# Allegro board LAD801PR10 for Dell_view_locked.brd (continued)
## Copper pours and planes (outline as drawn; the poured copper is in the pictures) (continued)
GND on IN2 (solid shape): 12.56,102.92 12.3,102.19 11.64,101.79 11.4,102.02 9.35,102.02 9.09,101.76 7.96,101.76 7.96,101.52 7.62,100.7 6.8,100.36 6,100.36 5.18,100.7 4.84,101.52 4.84,101.76 3.86,101.76 3.6,102.02 1.68,102.02 1.42,101.76 1,101.76 0.76,101.66 0.66,101.42 0.66,100.8 0.76,100.56 1,100.46 1.8,100.46 2.83,100.03 3.26,99 3.26,98.15 3.68,97.73 11.7,97.73 13.28,96.16 13.28,93.95 12.8,93.46 9.65,93.46 9.65,94.75 9.07,95.44 8.29,94.99 8.28,94.95 1,94.95 0.44,95.19 0.2,95.75 0.2,96.9 0.44,97.46 1,97.7 1.8,97.7 2.51,97.99 2.8,98.7 2.8,99 2.51,99.71 1.8,100 1,100 0.44,100.24 0.2,100.8 0.2,101.42 0.44,101.99 1,102.22 5,102.22 5.21,102.13 5.3,101.92 5.3,101.52 5.5,101.03 6,100.82 6.8,100.82 7.3,101.03 7.5,101.52 7.5,101.92 7.59,102.13 7.8,102.22 11.4,102.22 11.9,102.43 12.1,102.92 12.1,103.62 12.56,103.62
GND on IN2 (solid shape): outline of 339 points within 77.84,101.24 84.51,110.87
GND on IN2 (solid shape): outline of 281 points within 0.2,0.2 231.7,138.3
GND on IN3 (solid shape): 67.32,125.11 67.32,121.66 66.87,121.21 65.81,121.21 65.6,121.01 65.6,119.97 65.95,119.63 67.11,119.63 67.32,119.42 67.32,117.11 67.03,116.82 61.73,116.82 61.48,117.07 61.48,124.47 62.69,125.68 66.75,125.68
GND on IN3 (solid shape): 158.72,71.6 158.72,69.45 157.12,67.85 157.12,63.21 156.74,62.83 154.92,62.83 151.79,65.96 151.79,68.12 152.24,68.57 153.59,68.57 155.44,70.41 155.44,71.36 155.8,71.72 155.83,71.72 155.86,71.75 158.56,71.75
GND on IN3 (solid shape): 158.77,81.33 158.77,79.08 158.39,78.7 158.39,74.51 158.32,74.45 152.13,74.45 151.94,74.63 151.94,78.15 152.3,78.51 154.26,78.51 154.4,78.64 154.71,78.64 155.49,79.42 155.49,80.73 156.13,81.37 156.18,81.37 156.3,81.49 158.6,81.49
GND on IN3 (solid shape): 14.7,31.39 14.7,29.2 13.71,28.21 13.71,26.97 13.46,26.71 2.49,26.71 2.5,26.81 2.5,26.9 2.5,30.17 2.74,30.73 3.3,30.96 12.28,30.96 12.79,31.18 12.98,31.69 14.4,31.69
GND on IN3 (solid shape): 14.57,52.82 14.57,51.58 13.96,50.97 13.96,47.03 14.42,46.58 14.42,45.32 13.44,44.34 12.98,44.34 12.77,44.83 12.28,45.04 3.3,45.04 2.74,45.27 2.5,45.83 2.5,51.87 2.74,52.43 3.3,52.66 12.28,52.66 12.73,52.82 12.97,53.23 14.17,53.23
GND on IN3 (solid shape): 13.53,80.13 13.53,69.33 14.47,68.39 14.47,67.15 14.01,66.69 12.53,66.69 12.41,66.72 12.28,66.74 4.3,66.74 3.74,66.97 3.5,67.53 3.5,75.1 3.18,75.92 1.87,76.55 1.66,77.09 1.66,78.25 1.9,78.81 2.46,79.05 8.28,79.05 8.29,79.01 9.07,78.56 9.65,79.25 9.65,80.82 12.85,80.82
GND on IN3 (solid shape): 12.56,102.92 12.3,102.19 11.64,101.79 11.4,102.02 9.35,102.02 9.09,101.76 7.96,101.76 7.96,101.52 7.62,100.7 6.8,100.36 6,100.36 5.18,100.7 4.84,101.52 4.84,101.76 3.86,101.76 3.6,102.02 1.68,102.02 1.42,101.76 1,101.76 0.76,101.66 0.66,101.42 0.66,100.8 0.76,100.56 1,100.46 1.8,100.46 2.83,100.03 3.26,99 3.26,98.15 3.68,97.73 11.7,97.73 13.28,96.16 13.28,93.95 12.8,93.46 9.65,93.46 9.65,94.75 9.07,95.44 8.29,94.99 8.28,94.95 1,94.95 0.44,95.19 0.2,95.75 0.2,96.9 0.44,97.46 1,97.7 1.8,97.7 2.51,97.99 2.8,98.7 2.8,99 2.51,99.71 1.8,100 1,100 0.44,100.24 0.2,100.8 0.2,101.42 0.44,101.99 1,102.22 5,102.22 5.21,102.13 5.3,101.92 5.3,101.52 5.5,101.03 6,100.82 6.8,100.82 7.3,101.03 7.5,101.52 7.5,101.92 7.59,102.13 7.8,102.22 11.4,102.22 11.9,102.43 12.1,102.92 12.1,103.62 12.56,103.62
GND on IN3 (solid shape): outline of 279 points within 0.2,0.2 231.7,138.3
GND on GND1: outline of 262 points within 0.2,0.2 231.7,138.3
GND on VCC: outline of 213 points within 1.17,17.35 230.73,137.33
GND on VCC: 2.77,1.17 2.77,6.93 3.65,6.93 5.27,7.69 5.74,9.42 26.6,9.42 27.62,10.44 31.2,10.44 31.2,1.17
GND on GND2: outline of 263 points within 0.2,0.2 231.7,138.3
VCCSA_B+ on BOTTOM (solid shape): 150.08,63.13 150.08,62.73 149.55,62.73 149.55,62.29 150.08,62.29 150.08,61.57 149.69,61.17 149.69,58 149.56,57.87 148.29,57.87 146.39,55.97 146.32,55.97 146.01,56.28 146.01,56.35 146.39,56.73 146.39,56.86 145.81,57.43 145.81,58.06 145.83,58.08 146.71,59.76 146.9,61.66 146.89,61.68 148.42,63.21 150,63.21
+BIF_VDDC on TOP (solid shape): 114.59,118.51 114.59,117.8 114.59,117.75 114.5,117.66 114,117.66 113.86,117.8 113.15,117.8 113.06,117.89 111.99,117.89 111.81,118.07 111.81,118.6 111.99,118.78 114.32,118.78
+BIF_VDDC on TOP (solid shape): 112.42,124.54 112.42,123.86 113.02,123.25 113.02,123.04 112.97,123.04 112.97,122.94 112.66,122.63 111.01,122.63 110.77,122.88 110.79,122.91 110.79,123.28 110.46,123.45 110.38,123.48 110.35,123.56 110.35,124.63 110.38,124.67 112.29,124.67
+BIF_VDDC on IN3 (solid shape): outline of 433 points within 110.73,117.8 115.31,123.81
+DCBAT_LCD on TOP (solid shape): 229.17,52.71 229.17,49.67 228.73,49.23 225.07,49.23 224.78,49.52 224.78,49.58 224.68,49.68 223.31,49.68 223.11,49.88 223.11,51.43 223.37,51.69 225.24,51.69 225.6,52.05 225.6,52.76 226.02,53.18 228.7,53.18
+DCBAT_LCD on BOTTOM (solid shape): 225.45,50.32 225.45,49.45 225.34,49.34 223.52,49.34 223.4,49.45 223.4,50.32 223.65,50.57 225.2,50.57
+LAN_VDD33 on TOP (solid shape): 39.14,115.59 39.14,113.8 38.76,113.42 36.71,113.42 36.59,113.53 36.59,115.28 36.77,115.46 37.86,115.46 38.12,115.72 39.01,115.72
+LAN_VDD33 on BOTTOM (solid shape): 37.36,115.4 37.74,115.4 37.86,115.28 37.86,114.45 37.74,114.32 36.84,114.32 36.4,114.76 36.4,115.47 36.47,115.53 37.23,115.53
+LAN_VDD33 on BOTTOM (solid shape): 30.38,121.51 30.82,121.51 30.82,122.04 31.1,122.04 31.14,122 31.14,120.4 31.04,120.29 28.44,120.29 28.34,120.4 28.34,121.27 28.57,121.51 29.91,121.51 29.98,121.58 29.98,121.95 30.07,122.04 30.38,122.04
+LAN_VDD33 on IN1 (solid shape): 37.32,120.25 37.32,115.79 37.57,115.53 38.03,115.53 38.2,115.37 38.2,114.23 38.07,114.1 36.37,114.1 36.29,114.19 36.29,119.63 36.27,119.65 36.27,119.97 35.71,120.54 34.66,120.54 34.17,120.05 30.02,120.05 29.96,120.11 29.96,120.76 30.31,121.1 33.42,121.1 33.93,121.62 35.95,121.62
+LAN_VDDREG on TOP (solid shape): 37.49,119.59 37.49,118.76 37.29,118.57 35.52,118.57 35.45,118.64 35.45,119.78 35.2,120.03 35.2,120.22 35.39,120.41 36.66,120.41
+LAN_VDDREG on BOTTOM (solid shape): 36.02,119.97 36.02,119.59 35.9,119.46 35.9,118.57 35.83,118.51 35.71,118.51 35.64,118.57 35.64,119.46 35.45,119.65 35.45,119.84 35.2,120.1 35.2,120.29 35.33,120.41 35.58,120.41
+LCDVDD on BOTTOM (solid shape): 223.91,26.61 223.91,25.06 224.29,24.68 224.66,24.68 224.99,24.35 224.99,24.1 224.7,23.81 224.32,23.81 224.03,23.93 223.76,23.79 223.08,23.79 222.21,24.66 222.21,26.73 222.28,26.8 223.72,26.8
+LCDVDD_LCD on TOP (solid shape): 223.22,47.76 224.02,47.76 224.1,47.69 224.1,46.29 224.05,46.24 222.34,46.24 222.14,46.44 222.14,47.83 222.27,47.96 223.03,47.96
+LCDVDD_LCD on BOTTOM (solid shape): 223.34,47.76 224.49,47.76 224.58,47.67 224.58,46.44 224.5,46.37 222.46,46.37 222.33,46.49 222.33,46.5 222.2,46.63 222.2,47.73 222.38,47.91 223.19,47.91
+LCDVDD_LCD on BOTTOM (solid shape): 225.06,28.78 225.06,27.77 224.82,27.53 224.65,27.53 224.43,27.6 224.23,27.49 222.29,27.49 222.21,27.57 222.21,28.74 222.38,28.9 224.94,28.9
+LCDVDD_LCD on IN1 (solid shape): 223.6,47.71 223.6,47.64 223.61,47.63 223.61,45.6 223.53,45.52 222.6,45.52 222.54,45.58 222.3,45.58 222.02,45.87 222.02,47.77 222.27,48.02 223.29,48.02
+LCDVDD_LCD on IN1 (solid shape): 223.56,28.75 224.78,28.75 224.94,28.59 224.94,27.64 224.67,27.37 223.42,27.37 222.23,28.56 222.23,28.9 222.73,29.4 222.91,29.4
+LCDVDD_LCD on IN3 (solid shape): 226.38,28.62 226.38,27.02 226.19,26.83 224.01,26.83 223.9,26.94 223.9,28.64 223.98,28.72 226.28,28.72
+LCDVDD_LCD on IN3 (solid shape): 224.75,48.21 224.75,47.07 224.37,46.69 222.46,46.69 222.21,46.94 222.21,48.02 222.33,48.15 223.03,48.15 223.29,48.41 224.56,48.41
+PCIE_VDDC on TOP (solid shape): 116.42,123.97 116.42,122.94 116.81,122.54 116.81,121.19 116.65,121.03 116.65,119.75 116.31,119.4 115.51,119.4 115.08,118.98 111.43,118.98 110.97,119.44 110.97,120.23 111.06,120.31 114.22,120.31 114.38,120.48 114.38,121.29 114.24,121.43 114,121.43 113.94,121.49 113.94,121.67 114.92,121.67 114.92,121.61 114.92,121.56 114.94,121.51 114.96,121.46 114.99,121.42 115.03,121.38 115.07,121.34 115.12,121.32 115.17,121.3 115.22,121.29 115.27,121.28 115.33,121.29 115.38,121.3 115.43,121.32 115.47,121.34 115.52,121.38 115.55,121.42 115.58,121.46 115.6,121.51 115.62,121.56 115.63,121.61 115.63,121.67 115.62,121.72 115.6,121.77 115.58,121.82 115.55,121.86 115.52,121.9 115.47,121.93 115.43,121.96 115.38,121.98 115.33,121.99 115.27,122 115.22,121.99 115.17,121.98 115.12,121.96 115.07,121.93 115.03,121.9 114.99,121.86 114.96,121.82 114.94,121.77 114.92,121.72 114.92,121.67 113.94,121.67 113.94,122.95 114.19,123.21 114.19,123.53 114,123.72 113.62,123.72 113.6,123.69 113.58,123.69 113.48,123.59 113.43,123.59 113.16,123.86 113.11,123.93 113.11,124.03 114,124.92 115.46,124.92
+PCIE_VDDC on BOTTOM (solid shape): 105.68,102.19 105.68,101.17 106.11,100.74 106.11,99.13 105.65,98.67 105.65,97.64 106.11,97.17 106.11,96.14 105.87,95.9 103.61,95.9 103.55,95.97 103.55,97.33 103.71,97.48 103.71,101.29 103.97,101.55 103.99,101.56 104.19,101.66 104.29,101.86 104.29,101.88 104.67,102.25 105.62,102.25
+PCIE_VDDC on IN1 (solid shape): outline of 1893 points within 101.87,100.79 117.05,123.88
+SPLL_VDDC on TOP (solid shape): 121.15,105.13 121.15,104.71 122.24,103.62 122.27,103.54 122.23,103.47 122.12,103.04 122.52,102.83 122.54,102.84 122.64,102.74 122.64,99.84 122.45,99.65 121.88,99.65 121.68,99.85 121.68,101.74 121.06,102.36 121.06,102.46 121.09,102.54 121.18,102.56 121.62,102.99 121.03,103.17 121,103.16 120.96,103.17 120.43,103.71 120.43,104.89 120.43,104.89 120.43,105.13 120.61,105.31 120.97,105.31
+VGA_CORE on TOP (solid shape): 105.7,107.04 105.7,106.69 106,106.39 106,106.01 106.42,105.58 106.42,105.32 104.58,103.48 103.66,102.56 103.19,102.56 102.47,103.28 102.47,103.3 102,103.77 102,104.84 104.85,107.7 105.04,107.7
+VGA_CORE on TOP (solid shape): 111.53,105.53 111.53,103.98 111.38,103.82 111.32,103.61 111.32,102.62 111.47,102.47 111.45,102.44 111.45,101.89 111.37,101.89 111.37,101.66 111.37,101.65 111.35,101.51 111.37,101.37 111.37,101.36 111.37,101.3 111.26,101.18 107.91,101.18 107.65,101.43 107.65,102.32 108.22,102.89 108.22,103.2 108.32,103.3 108.32,103.3 108.86,103.85 109.26,103.85 109.56,104.15 109.56,104.86 110.1,105.4 110.1,105.58 110.29,105.77 111.29,105.77
+VGA_CORE on TOP (solid shape): outline of 120 points within 79.59,110.05 89.25,131.84
+VGA_CORE on BOTTOM (solid shape): 108.16,113.18 108.16,113.15 108.22,112.62 108.75,112.67 108.92,112.67 109.11,112.48 109.11,112.08 109.11,112.07 109.14,111.71 109.46,111.54 109.48,111.54 109.56,111.46 109.75,111.46 110.07,111.14 110.07,111.02 109.32,110.27 109.31,110.27 109.19,110.19 109.11,110.06 109.1,110.05 108.48,109.43 107.53,109.43 107.4,109.3 107.07,109.3 107.01,109.35 106.94,109.39 106.93,109.39 106.89,109.43 106.89,109.75 106.94,109.8 106.95,109.8 107.09,109.88 107.18,110.02 107.18,110.04 107.5,110.36 107.65,110.72 107.37,111 107.35,111 107.16,111.19 107.17,111.22 107.18,111.4 107.08,111.56 107.08,112.01 107.14,112.07 107.14,112.34 107.19,112.56 107.08,112.76 107.08,113.05 107.4,113.37 107.97,113.37
+VGA_CORE on BOTTOM (solid shape): outline of 139 points within 79.52,109.62 90.5,132.42
+VGA_CORE on BOTTOM (solid shape): 116.88,117.73 116.88,117.71 116.91,117.57 116.99,117.45 116.99,116.99 116.88,116.72 116.99,116.45 116.99,115.99 116.88,115.72 116.99,115.45 116.99,114.99 116.88,114.72 116.99,114.45 116.99,114.18 116.88,113.92 116.99,113.65 116.99,113.18 116.91,113.08 116.88,112.96 116.88,112.94 116.61,112.67 116.59,112.65 116.51,112.42 116.61,112.19 116.61,111.78 116.42,111.59 116.1,111.59 115.6,112.08 115.6,112.09 115.53,112.19 115.43,112.26 115.42,112.26 115.02,112.67 115.02,113.05 115.21,113.24 115.49,113.24 115.65,113.08 115.7,113.08 115.71,113.07 116.19,113.26 116,113.73 115.99,113.73 115.4,114.32 115.02,114.32 114.89,114.45 114.89,114.89 115.15,115.14 115.21,115.14 115.46,115.39 115.46,115.39 115.63,115.81 115.29,116.1 115.27,116.1 114.83,116.54 114.83,116.84 114.91,116.92 114.92,116.92 115.01,116.97 115.09,117.05 115.45,117.05 115.99,117.04 115.91,117.58 115.91,117.82 115.94,117.84 116.06,117.9 116.14,118 116.61,118
+VGA_CORE on IN1 (solid shape): outline of 106 points within 79.78,110.03 89.4,131.67
+VGA_CORE on IN1 (solid shape): outline of 2387 points within 104.62,101.37 117.05,118.6
+VGA_CORE on IN2 (solid shape): outline of 7671 points within 79.14,101.21 117.37,130.9
+VGA_CORE on IN3 (solid shape): outline of 116 points within 79.83,110.22 88.74,130.6
+VGA_CORE on IN3 (solid shape): outline of 1788 points within 104.53,104.06 115.04,117.53
+VGA_CORE on VCC: 96.52,100.54 85.66,111.4 80.71,111.4 79.77,112.33 79.77,128.18 82.1,130.51 87.04,130.51 90.65,126.9 115.27,126.9 115.27,117.2 117.05,115.43 117.05,113.22 116.88,113.05 116.63,113.05 116.1,112.52 116.1,110.73 116.86,109.96 116.86,107.95 115.27,106.36 115.27,103.27 113.51,103.27 110.85,100.54
ACIN_CHG on BOTTOM (solid shape): 192.86,34.48 192.86,34.37 192.55,34.06 192.55,33.49 192.49,33.42 191.92,33.42 191.79,33.55 191.79,33.84 191.79,33.85 191.81,33.95 191.79,34.06 191.79,34.07 191.79,34.38 191.92,34.5 191.95,34.54 192.8,34.54
ADJ_2.5V on BOTTOM (solid shape): 44.61,9.07 44.61,8.16 44.84,7.93 45.96,7.93 46.29,7.6 47.82,7.6 48.03,7.4 48.03,7.08 47.85,6.9 46.01,6.9 45.69,7.22 44.1,7.22 43.96,7.36 43.96,9.04 44.03,9.1 44.58,9.1
AUD_AGND on GND1: 4.4,9.93 4.05,10.13 3.65,10.2 2.3,10.2 1.95,10.35 1.8,10.7 1.8,13.67 1.95,14.02 2.3,14.16 12.45,14.16 13.15,14.77 12.65,15.54 12.65,20.99 13.15,21.77 12.45,22.37 1.2,22.37 0.85,22.52 0.7,22.87 0.7,24.91 0.91,25.44 1.42,25.7 1.89,25.85 2.27,26.18 12.42,26.18 14.64,23.96 15.77,23.96 17.16,24.73 23.75,24.73 23.94,24.92 24.79,24.92 25.23,24.48 25.23,22.68 24.91,22.36 24.91,17.75 25.24,17.42 28.47,17.42 28.47,16.01 28.34,15.88 28.35,14.15 28.34,13.62 28.48,13.26 28.77,12.96 28.77,12.96 28.84,12.89 28.92,12.81 28.92,12.81 29.02,12.81 29.13,12.81 29.13,12.81 31.93,12.83 32.04,12.82 32.04,12.83 32.11,12.9 33.34,14.12 33.34,14.48 33.36,17.24 33.36,17.45 33.36,17.66 33.21,17.8 33.03,17.8 32.71,18.12 30.04,18.12 29.86,18.3 29.86,18.83 30.04,19.01 31.92,19.01 32.04,18.88 34.46,18.87 36.39,16.95 36.4,15.24 32.11,10.95 27.41,10.95 26.39,9.93
AUD_AGND on VCC: 5.58,9.93 4.8,10.83 3.65,11.17 2.77,11.17 2.77,13.2 12.45,13.2 14,14.24 13.62,16.06 13.62,20.48 14,22.3 12.45,23.34 1.67,23.34 1.67,24.76 2.7,25.24 3.35,26.18 12.42,26.18 14.64,23.96 15.77,23.96 17.16,24.73 23.75,24.73 23.94,24.92 24.79,24.92 25.23,24.48 25.23,22.68 24.91,22.36 24.91,17.75 25.24,17.42 28.47,17.42 28.47,16.01 28.34,15.88 28.35,14.15 28.34,13.62 28.48,13.26 28.77,12.96 28.77,12.96 28.84,12.89 28.92,12.81 28.92,12.81 29.02,12.81 29.13,12.81 29.13,12.81 31.93,12.83 32.04,12.82 32.04,12.83 32.11,12.9 33.34,14.12 33.34,14.48 33.36,17.24 33.36,17.45 33.36,17.66 33.21,17.8 33.03,17.8 32.71,18.12 30.04,18.12 29.86,18.3 29.86,18.83 30.04,19.01 31.92,19.01 32.04,18.88 34.46,18.87 36.39,16.95 36.4,15.24 32.11,10.95 27.41,10.95 26.39,9.93
AUD_AGND on GND2: 4.4,9.93 4.05,10.13 3.65,10.2 2.3,10.2 1.95,10.35 1.8,10.7 1.8,13.67 1.95,14.02 2.3,14.16 12.45,14.16 13.15,14.77 12.65,15.54 12.65,20.99 13.15,21.77 12.45,22.37 1.2,22.37 0.85,22.52 0.7,22.87 0.7,24.21 0.71,24.22 16.23,24.22 17.16,24.73 23.75,24.73 23.94,24.92 24.79,24.92 25.23,24.48 25.23,22.68 24.91,22.36 24.91,17.75 25.24,17.42 28.47,17.42 28.47,16.01 28.34,15.88 28.35,14.15 28.34,13.62 28.48,13.26 28.77,12.96 28.77,12.96 28.84,12.89 28.92,12.81 28.92,12.81 29.02,12.81 29.13,12.81 29.13,12.81 31.93,12.83 32.04,12.82 32.04,12.83 32.11,12.9 33.34,14.12 33.34,14.48 33.36,17.24 33.36,17.45 33.36,17.66 33.21,17.8 33.03,17.8 32.71,18.12 30.04,18.12 29.86,18.3 29.86,18.83 30.04,19.01 31.92,19.01 32.04,18.88 34.46,18.87 36.39,16.95 36.4,15.24 32.11,10.95 27.41,10.95 26.39,9.93
AUD_SPK_L+ on TOP (solid shape): 34.05,9.1 34.05,7.96 33.8,7.71 32.48,7.71 32.35,7.83 32.35,8.92 32.59,9.17 33.99,9.17
AUD_SPK_L+ on TOP (solid shape): 33.04,19.9 33.04,19.65 32.91,19.52 31.81,19.52 31.81,19.52 31.07,19.52 30.94,19.65 30.05,19.65 29.99,19.71 29.99,19.84 30.05,19.9 31.9,19.9 31.96,19.96 32.98,19.96
AUD_SPK_L+ on IN1 (solid shape): 35.13,9.36 35.13,9.1 33.99,7.96 33.36,7.96 33.23,8.09 33.23,8.79 34.31,9.87 34.63,9.87
AUD_SPK_L+ on IN1 (solid shape): 33.26,19.93 35.99,19.93 36.53,19.39 36.53,18.95 36.5,18.92 35.17,18.92 34.75,19.33 31.9,19.33 31.77,19.45 31.77,19.84 31.9,19.96 33.23,19.96
AUD_SPK_L+_C on TOP (solid shape): 26.56,8.72 27.7,8.72 28.15,8.28 29.17,8.28 29.23,8.34 29.23,8.91 29.36,9.04 31.95,9.04 32.15,8.84 32.15,7.89 31.71,7.45 25.99,7.45 25.23,8.22 25.23,8.98 25.55,9.29 25.99,9.29
AUD_SPK_L+_C on BOTTOM (solid shape): 10.12,7.58 10.12,7.58 10.12,4.91 9.99,4.79 9.67,4.79 9.42,5.04 9.42,7.64 9.55,7.77 9.93,7.77
AUD_SPK_L+_C on IN1 (solid shape): 10.95,7.74 10.95,6.75 10.79,6.59 9.46,6.59 9.37,6.68 9.37,7.74 9.41,7.79 10.9,7.79
AUD_SPK_L+_C on IN1 (solid shape): 26.1,8.9 26.1,8.28 25.06,7.24 23.8,7.24 23.69,7.35 23.69,8.2 23.82,8.33 24.43,8.33 25.28,9.18 25.82,9.18
AUD_SPK_L- on TOP (solid shape): 34.05,6.95 34.05,5.8 33.8,5.55 32.53,5.55 32.37,5.71 32.37,6.79 32.59,7.01 33.99,7.01
AUD_SPK_L- on TOP (solid shape): 33.04,20.47 33.04,20.15 32.98,20.09 32.71,20.09 32.61,20.11 32.5,20.09 32.46,20.09 32.35,20.11 32.24,20.09 32.13,20.09 32.02,20.11 31.91,20.09 31.83,20.09 31.77,20.03 30.05,20.03 29.99,20.09 29.99,20.22 30.05,20.28 31.64,20.28 31.96,20.6 32.91,20.6
AUD_SPK_L- on IN1 (solid shape): 35.32,7.64 35.32,7.52 33.86,6.06 33.86,5.87 33.74,5.74 33.17,5.74 32.98,5.93 32.98,6.69 34.5,8.22 34.75,8.22
AUD_SPK_L- on IN1 (solid shape): 35.07,21.17 35.07,20.22 35.01,20.15 32.02,20.15 31.9,20.28 31.9,20.41 32.34,20.85 33.93,20.85 34.31,21.23 35.01,21.23
AUD_SPK_L-_C on TOP (solid shape): 30.06,7.13 31.96,7.13 32.15,6.94 32.15,6.05 32.08,5.98 30,5.98 29.96,6.02 29.46,6.02 29.1,6.37 28.09,6.37 27.32,5.61 26.63,5.61 26.18,5.17 25.61,5.17 25.42,5.36 25.42,6.25 25.9,6.73 26.23,6.81 26.34,7.14 30.05,7.14
AUD_SPK_L-_C on BOTTOM (solid shape): 9.16,7.7 9.16,4.91 9.1,4.85 8.59,4.85 8.4,5.04 8.4,7.7 8.47,7.77 9.1,7.77
AUD_SPK_L-_C on IN1 (solid shape): 9.18,7.59 9.18,5.22 7.97,5.22 7.97,7.57 8.19,7.79 8.97,7.79
AUD_SPK_L-_C on IN1 (solid shape): 25.9,6.73 26.15,6.47 26.15,5.61 25.93,5.38 24.6,5.38 24.41,5.58 24.41,6.65 24.49,6.73 25.88,6.73
AUD_SPK_R+ on TOP (solid shape): 34.05,5.23 34.05,4.02 33.93,3.9 32.53,3.9 32.28,4.15 32.28,5.11 32.53,5.36 33.93,5.36
AUD_SPK_R+ on TOP (solid shape): 33.36,21.99 33.36,21.49 33.23,21.36 31.64,21.36 31.13,20.85 30.05,20.85 29.99,20.92 29.99,21.04 30.05,21.11 30.82,21.11 30.84,21.13 30.94,21.13 31.96,22.15 33.2,22.15
AUD_SPK_R+ on IN1 (solid shape): 35.39,5.8 35.39,5.74 34.31,4.66 34.31,4.21 34.18,4.09 33.55,4.09 33.36,4.28 33.36,5.17 34.5,6.31 34.88,6.31
AUD_SPK_R+ on IN1 (solid shape): 34.56,22.76 34.56,21.93 34.44,21.8 33.74,21.8 33.36,21.42 32.47,21.42 32.34,21.55 32.34,21.75 32.4,21.82 32.4,21.86 33.37,22.82 34.5,22.82
AUD_SPK_R+_C on TOP (solid shape): 32.15,4.97 32.15,3.76 31.84,3.45 26.61,3.45 26.48,3.58 26.24,3.58 26,3.83 25.99,3.83 25.93,3.89 24.79,3.89 24.72,3.83 24.34,3.83 24.21,3.96 24.21,4.84 24.35,4.98 26.37,4.98 26.63,4.72 27.8,4.72 28.31,4.21 28.69,4.21 28.82,4.34 29.55,4.34 29.61,4.4 30.24,5.04 32.08,5.04
AUD_SPK_R+_C on BOTTOM (solid shape): 12.34,6.24 12.34,3.83 12.25,3.74 11.49,3.74 11.42,3.8 11.42,6.22 11.64,6.43 12.15,6.43
AUD_SPK_R+_C on IN3 (solid shape): 12.69,5.75 12.69,3.96 12.48,3.74 11.54,3.74 11.46,3.82 11.46,5.78 11.53,5.85 12.59,5.85
AUD_SPK_R+_C on IN3 (solid shape): 24.96,4.74 24.96,4.06 24.66,3.76 23.42,3.76 23.36,3.83 23.36,4.85 23.38,4.88 24.81,4.88
AUD_SPK_R- on TOP (solid shape): 34.09,2.98 34.09,1.83 33.83,1.58 32.72,1.58 32.37,1.93 32.37,2.94 32.47,3.04 34.02,3.04
AUD_SPK_R- on TOP (solid shape): 32.66,21.17 32.66,20.79 32.59,20.72 31.64,20.72 31.32,20.41 30.05,20.41 29.99,20.47 29.99,20.6 30.12,20.73 31.19,20.73 31.25,20.79 31.26,20.79 31.7,21.23 31.74,21.23 31.78,21.23 32.59,21.23
AUD_SPK_R- on IN1 (solid shape): 32.28,22.12 32.28,21.87 32.09,21.68 32.09,21.3 32.21,21.17 32.21,20.98 31.58,20.34 31.2,20.34 30.88,20.66 30.88,21.99 31.51,22.63 31.77,22.63
AUD_SPK_R- on IN1 (solid shape): 35.83,4.15 35.83,4.02 34.12,2.31 34.12,1.77 33.92,1.57 33.4,1.57 33.29,1.68 33.29,2.94 34.94,4.6 35.39,4.6
AUD_SPK_R-_C on TOP (solid shape): 30.62,3.12 32.03,3.12 32.15,3 32.15,1.92 31.97,1.74 30.24,1.74 29.61,2.37 28.47,2.37 27.7,1.61 27.01,1.61 26.72,1.33 24.37,1.33 24.15,1.54 24.15,2.49 24.28,2.62 24.59,2.62 24.72,2.49 26.05,2.49 26.37,2.82 26.48,2.82 26.8,3.14 30.6,3.14
AUD_SPK_R-_C on BOTTOM (solid shape): 11.13,6.3 11.13,3.83 10.94,3.64 10.56,3.64 10.5,3.71 10.5,6.37 10.62,6.5 10.94,6.5
AUD_SPK_R-_C on IN3 (solid shape): 11.29,4.6 11.29,2.41 11.23,2.35 10.41,2.35 10.26,2.5 10.26,4.45 10.48,4.67 11.21,4.67
AUD_SPK_R-_C on IN3 (solid shape): 24.9,2.7 24.9,1.7 24.7,1.49 23.53,1.49 23.35,1.67 23.35,2.73 23.5,2.88 24.73,2.88
BST1_VGA on TOP (solid shape): 56.68,121.48 56.68,121.39 56.66,121.36 56.66,121.12 57.23,120.55 57.8,120.55 57.93,120.67 57.93,121.05 58.57,121.05 58.63,120.99 58.63,120.1 58.44,119.91 57.36,119.91 56.09,121.18 55.84,121.18 55.67,121.35 55.67,121.49 55.72,121.54 56.62,121.54
BST2_VGA on TOP (solid shape): 58.63,126.01 58.63,125.18 58.57,125.12 57.99,125.12 57.93,125.18 57.93,125.5 57.74,125.69 57.3,125.69 56.72,125.12 56.72,125.06 56.6,124.93 55.72,124.93 55.67,124.98 55.67,125.08 55.73,125.14 56.11,125.14 57.04,126.07 58.57,126.07
BST_1.2V on BOTTOM (solid shape): 88.22,108.93 88.22,107.4 88.03,107.21 88.03,106.07 87.97,106.01 87.9,106.01 87.84,106.07 87.84,107.53 87.52,107.85 87.52,108.93 87.59,108.99 88.16,108.99
BST_1.2V_R on BOTTOM (solid shape): 86.82,108.98 86.82,108.16 86.76,108.1 86.19,108.1 85.81,108.48 85.3,108.48 85.22,108.55 85.22,108.97 85.3,109.05 86.76,109.05
BST_3V on BOTTOM (solid shape): 174.8,45.2 174.8,43.78 174.72,43.7 174.59,43.7 174.52,43.78 174.52,44.22 173.5,45.24 172.9,45.24 172.85,45.29 172.85,45.92 172.91,45.98 174.01,45.98
BST_5V on BOTTOM (solid shape): 177.56,36.22 177.56,34.69 177.5,34.63 177.5,33.79 177.42,33.7 177.31,33.7 177.23,33.78 177.23,34.77 176.91,35.1 176.91,36.2 176.99,36.28 177.5,36.28
BST_+1.35VGPU on BOTTOM (solid shape): 154.58,93.18 154.58,92.61 155.34,91.84 155.34,91.21 155.21,91.08 155.09,91.08 153.69,92.48 153.69,93.18 153.75,93.24 154.51,93.24
BST_+1.35VGPU_R on BOTTOM (solid shape): 154.64,94.51 154.64,93.94 154.58,93.88 152.93,93.88 152.74,94.07 152.74,94.51 152.86,94.64 154.51,94.64
BST_+1VALW on BOTTOM (solid shape): 149.75,45.55 149.79,45.51 149.79,43.83 149.72,43.76 149.61,43.76 149.54,43.83 149.54,44.11 148.29,45.36 148.29,46 148.35,46.06 149.24,46.06
BST_+1VALW_R on BOTTOM (solid shape): 149.31,47.39 149.31,46.82 149.24,46.76 148.35,46.76 148.22,46.62 148.22,46.49 148.04,46.32 147.47,46.32 147.4,46.38 147.4,46.89 147.97,47.46 149.24,47.46
CORE_SW on BOTTOM (solid shape): 156.36,72.17 156.61,72.17 156.61,70.16 155.29,70.16 154.55,69.42 152.23,69.42 152.23,69.42 152.23,70.83 153.12,70.83 153.12,71.59 152.23,71.59 152.23,71.71 152.23,71.72 152.23,72.92 152.29,72.99 155.55,72.99
CPU_B+ on TOP (solid shape): 160.4,72.37 160.4,69.07 159.47,68.14 159.47,63.21 159.15,62.89 157.75,62.89 157.44,63.21 157.44,67.21 157.18,67.46 157.18,68.74 157.24,68.79 158.22,68.79 158.87,69.45 158.87,72.41 159,72.54 160.23,72.54
CPU_B+ on TOP (solid shape): 160.45,82.06 160.45,74.58 160.16,74.29 158.72,74.29 158.64,74.37 158.64,78.54 158.89,78.79 158.89,79.17 158.9,79.24 158.89,79.3 158.89,80.13 158.9,80.2 158.89,80.27 158.89,81.09 158.9,81.16 158.89,81.23 158.89,82.02 159.05,82.19 160.33,82.19
CPU_B+ on BOTTOM (solid shape): 152.55,62.95 152.55,62.06 152.42,61.94 150.31,61.94 150.21,62.04 150.21,62.42 149.67,62.42 149.67,62.6 150.21,62.6 150.21,63.02 150.33,63.14 152.36,63.14
CPU_B+ on BOTTOM (solid shape): 159.73,83.07 159.73,82.19 160.45,82.19 160.47,82.17 160.47,78.78 161.18,78.07 164.82,78.07 166.35,76.54 166.35,75.9 166.87,75.9 166.87,75.45 166.35,75.45 166.35,74.7 166.87,74.7 166.87,74.25 166.35,74.25 166.35,73.48 166.35,73.45 168.49,71.3 168.49,70.13 170.24,68.38 170.24,65.56 169.02,64.35 160.74,64.35 159.15,62.76 157.75,62.76 157.37,63.14 157.37,65.37 157.21,65.53 157.21,68.78 157.23,68.8 158.54,68.8 158.87,69.13 158.87,72.5 158.91,72.54 159.28,72.54 159.39,72.65 159.39,73.36 159.5,73.46 159.59,73.46 159.68,73.38 159.68,72.63 159.77,72.54 160.34,72.54 160.4,72.48 160.4,69.4 160.69,69.11 163.28,69.11 163.58,69.41 163.9,69.41 164.36,69.46 164.15,69.87 164.1,69.87 164.1,71.21 164.09,71.22 164.09,71.46 163.85,71.46 163.71,71.6 163.71,74.2 162.71,75.21 160.36,75.21 159.53,74.38 158.58,74.38 158.51,74.45 158.51,75.17 158.64,75.3 158.64,78.57 158.92,78.86 158.92,82.18 158.94,82.19 159.37,82.19 159.45,82.28 159.45,83.06 159.53,83.14 159.66,83.14
CPU_B+ on IN1 (solid shape): 160.44,82.1 160.44,75.48 159.59,74.63 159.29,74.63 158.7,75.22 158.7,78.67 158.93,78.89 158.93,82.12 159.05,82.24 160.3,82.24
CPU_B+ on IN1 (solid shape): 160.39,72.39 160.39,68.9 159.95,68.46 159.95,64.32 159.55,63.92 158.53,63.92 158.25,64.21 158.25,68.73 158.89,69.37 158.89,72.48 158.93,72.52 160.26,72.52
CPU_B+ on IN2 (solid shape): 160.16,72.52 160.28,72.52 160.39,72.41 160.39,64.76 159.46,63.83 158.63,63.83 158.25,64.21 158.25,68.57 158.86,69.18 158.86,72.42 158.97,72.53 160.15,72.53
CPU_B+ on IN2 (solid shape): 160.46,82.03 160.46,75.19 159.84,74.57 159.46,74.57 158.71,75.32 158.71,78.54 158.92,78.75 158.92,82.08 159.02,82.17 160.32,82.17
CPU_B+ on IN3 (solid shape): 160.27,82.18 160.34,82.18 160.48,82.04 160.48,75.29 159.95,74.76 159.38,74.76 158.71,75.43 158.71,78.69 158.93,78.91 158.93,82.08 159.04,82.19 160.27,82.19
CPU_B+ on IN3 (solid shape): 160.44,72.35 160.44,68.6 160.2,68.36 160.2,64.77 159.46,64.04 158.43,64.04 158.14,64.34 158.14,68.5 158.86,69.23 158.86,72.41 158.98,72.53 160.26,72.53
DP_VSSR on IN3 (solid shape): outline of 280 points within 98.51,110.7 105.49,121.12
EN_2.5V on BOTTOM (solid shape): 54.31,8.78 54.31,7.26 53.97,6.91 51.48,6.91 51.3,7.09 51.3,7.42 51.47,7.59 53.46,7.59 53.69,7.82 53.69,8.83 53.77,8.91 54.19,8.91
GT_SW1 on BOTTOM (solid shape): 155.59,81.81 156.63,81.81 156.65,81.78 156.65,79.84 156.59,79.78 155.59,79.78 154.65,78.84 152.28,78.84 152.27,78.85 152.27,80.22 153.16,80.22 153.16,80.99 152.27,80.99 152.27,82.42 152.48,82.64 154.77,82.64
HDMI_PLL_GND on TOP (solid shape): 16.13,79.44 16.13,77.6 15.77,77.23 14.6,77.23 14.31,77.52 14.31,79.45 14.47,79.61 15.96,79.61
HDMI_PLL_GND on BOTTOM (solid shape): 15.51,88.74 15.51,81.54 15.52,81.53 15.52,79.21 15.33,79.02 14.35,79.02 14.14,79.23 14.14,88.68 14.33,88.87 15.39,88.87
IR_GND on BOTTOM (solid shape): 227.47,38.78 227.47,37.91 226.93,37.37 223.53,37.37 223.43,37.48 223.43,38.14 223.53,38.25 226.25,38.25 226.38,38.38 226.48,38.45 226.55,38.55 226.95,38.95 227.3,38.95
LDO_+1.35VGPU on BOTTOM (solid shape): 154.96,89.55 154.96,88.99 154.71,88.74 153.69,88.74 153.56,88.87 153.56,89.53 153.66,89.63 154.88,89.63
LDO_+1VALW on BOTTOM (solid shape): 149.45,42.26 149.45,41.72 149.35,41.62 147.82,41.62 147.72,41.72 147.72,42.03 148.02,42.33 149.38,42.33
LG1_VGA on TOP (solid shape): 68.73,116.76 68.77,116.72 68.77,115.76 68.6,115.59 67.71,115.59 67.52,115.78 67.52,115.79 67.46,115.85 67.46,116.72 67.61,116.87 68.61,116.87
LG1_VGA on TOP (solid shape): 57.55,122.71 57.57,122.71 57.6,122.68 58.41,122.68 58.57,122.52 58.57,122.32 58.44,122.2 57.68,122.2 57.42,122.45 56.79,122.45 56.72,122.52 55.71,122.52 55.64,122.58 55.64,122.71 55.71,122.77 57.49,122.77
LG1_VGA on BOTTOM (solid shape): 68.79,120.74 68.79,120.1 68.66,119.98 66.57,119.98 66.38,120.17 66.38,120.86 66.44,120.93 68.6,120.93
LG1_VGA on IN1 (solid shape): 60.03,122.64 60.03,122.01 59.77,121.75 58.12,121.75 57.49,122.39 57.49,122.52 57.68,122.71 58.63,122.71 58.69,122.77 59.9,122.77
LG1_VGA on IN1 (solid shape): 68.79,120.74 68.79,115.85 68.6,115.66 67.65,115.66 67.46,115.85 67.46,119.53 67.14,119.85 65.37,119.85 65.17,120.05 65.17,120.74 65.39,120.96 68.57,120.96
LG2_VGA on TOP (solid shape): 68.79,122.49 68.79,121.44 68.54,121.18 67.58,121.18 67.46,121.31 67.46,122.46 67.66,122.66 68.61,122.66
LG2_VGA on TOP (solid shape): 58.31,123.98 58.31,123.79 58.18,123.66 56.98,123.66 56.91,123.72 55.71,123.72 55.64,123.79 55.64,123.85 55.71,123.91 57.17,123.91 57.36,124.1 58.18,124.1
LG2_VGA on BOTTOM (solid shape): 68.79,126.94 68.79,126.06 68.56,125.83 67.63,125.83 67.46,126 67.46,126.96 67.58,127.08 68.65,127.08
LG2_VGA on IN1 (solid shape): 59.58,123.98 59.58,123.47 59.45,123.34 57.55,123.34 57.3,123.59 57.3,123.98 57.42,124.1 59.45,124.1
LG2_VGA on IN1 (solid shape): 68.77,126.93 68.77,126.54 68.66,126.43 68.66,121.37 68.5,121.21 67.68,121.21 67.53,121.35 67.53,122.72 67.69,122.87 67.69,125.47 67.59,125.56 67.59,126.68 67.6,126.69 67.6,126.84 67.81,127.06 68.64,127.06
LG_1.2V on BOTTOM (solid shape): 79.14,103.66 79.14,102.83 78.63,102.32 78.25,102.32 78.19,102.39 78.19,103.27 78.7,103.78 79.01,103.78
LG_1.2V on BOTTOM (solid shape): 86.63,105.81 86.76,105.81 86.82,105.75 86.82,105.69 86.76,105.62 86,105.62 85.81,105.81 85.36,105.81 85.11,106.07 85.11,106.26 85.3,106.45 86,106.45
LG_1.2V on IN3 (solid shape): 79.71,103.84 79.71,103.53 78.5,102.32 78.31,102.32 78.12,102.51 78.12,103.14 78.95,103.97 79.58,103.97
LG_1.2V on IN3 (solid shape): 86.19,106.26 86.19,105.94 86.06,105.81 85.05,105.81 85.04,105.81 84.89,105.81 84.48,105.4 84.38,105.4 84.16,105.62 84.16,106.07 84.54,106.45 86,106.45
LGATE_CHG on BOTTOM (solid shape): 204.11,35.9 204.11,35.27 203.92,35.08 203.16,35.08 203.03,35.2 203.03,36.03 203.09,36.09 203.92,36.09
LGATE_CHG on BOTTOM (solid shape): 198.58,36.22 198.58,35.96 198.2,35.58 197.38,35.58 197.31,35.52 196.12,35.52 196.07,35.57 196.07,35.69 196.13,35.74 197.09,35.74 197.63,36.28 198.52,36.28
LGATE_CHG on IN3 (solid shape): 198.58,37.11 198.58,36.03 198.39,35.83 197.57,35.83 197.5,35.9 197.5,37.04 197.7,37.23 198.46,37.23
LGATE_CHG on IN3 (solid shape): 204.04,36.79 204.11,36.72 204.11,35.77 203.98,35.64 203.16,35.64 202.97,35.83 202.97,36.59 203.28,36.91 203.92,36.91
LX1_VGA on TOP (solid shape): 57.3,122.32 57.61,122.01 58.63,122.01 58.76,121.88 58.76,121.37 58.63,121.25 57.65,121.25 57.59,121.27 56.85,122.01 56.74,122.01 56.69,122.04 56.6,122.13 55.71,122.13 55.64,122.2 55.64,122.26 55.71,122.32 56.73,122.32
LX1_VGA on TOP (solid shape): 74.54,120.58 74.54,118.55 74.89,118.2 78.5,118.2 78.7,118.01 78.7,113.49 78.66,113.48 78.45,113.15 78.66,112.82 78.7,112.81 78.7,112.23 78.31,111.84 73.11,111.84 72.79,112.16 72.79,115.85 72.66,115.97 69.74,115.97 69.49,116.23 69.49,120.61 69.81,120.93 74.19,120.93
LX1_VGA on BOTTOM (solid shape): 74.47,120.39 74.47,118.48 74.82,118.13 78.7,118.13 78.89,117.94 78.89,115.59 78.19,114.9 77.68,114.9 77.42,114.64 76.56,114.64 76.56,113.88 77.43,113.88 77.43,112.16 77.11,111.85 74.39,111.85 74.27,111.72 72.97,111.72 72.79,111.9 72.79,115.78 72.15,116.42 69.68,116.42 69.55,116.55 69.55,120.48 69.74,120.67 74.19,120.67
LX1_VGA on IN1 (solid shape): 75.01,115.72 75.01,114.39 74.95,114.32 73.23,114.32 73.11,114.45 73.11,115.72 73.17,115.78 74.95,115.78
LX1_VGA on IN1 (solid shape): 57.93,121.63 59.07,121.63 59.39,121.31 59.39,121.05 59.2,120.86 58.06,120.86 56.98,121.94 56.98,122.07 57.17,122.26 57.3,122.26
LX2_VGA on TOP (solid shape): 59.07,124.8 59.07,124.29 59.01,124.23 57.3,124.23 57.17,124.1 55.77,124.1 55.71,124.17 55.71,124.29 55.77,124.36 56.79,124.36 56.85,124.42 57.17,124.42 57.49,124.74 57.8,124.74 57.93,124.86 59.01,124.86
LX2_VGA on TOP (solid shape): outline of 109 points within 69.55,121.69 77.55,131.91
LX2_VGA on BOTTOM (solid shape): 77.49,131.66 77.49,127.84 76.6,127.84 76.6,127.08 77.49,127.08 77.49,124.17 76.03,122.71 75.01,122.71 74.06,121.75 69.74,121.75 69.55,121.94 69.55,125.88 69.56,125.89 69.56,126.2 69.69,126.33 69.74,126.33 69.91,126.49 74.42,126.49 74.69,126.77 74.69,128.36 74.31,128.74 73.04,128.74 72.85,128.93 72.85,131.97 73.03,132.15 77,132.15
LX2_VGA on IN1 (solid shape): 59.58,125.5 59.58,125.44 58.44,124.29 57.42,124.29 57.36,124.36 57.36,124.61 58.57,125.82 59.26,125.82
LX2_VGA on IN1 (solid shape): 75.46,125.31 75.46,124.74 75.39,124.67 73.49,124.67 73.36,124.8 73.36,125.44 73.68,125.75 75.01,125.75
LX_1.2V on BOTTOM (solid shape): 77.84,106.54 77.84,105.84 78.63,105.05 81.17,105.05 81.36,104.86 81.36,104.16 81.17,103.97 78.63,103.97 77.17,102.51 74.69,102.51 74.57,102.64 74.57,106.89 74.76,107.08 77.3,107.08
LX_1.2V on BOTTOM (solid shape): 86.95,106.96 87.14,106.96 87.2,106.89 87.2,106.89 87.24,106.85 87.24,106.11 87.24,106.09 87.18,106.03 87.05,106.03 86.63,106.45 86.51,106.45 85.55,107.4 85.37,107.4 85.24,107.53 85.24,108.04 85.3,108.1 85.81,108.1
LX_1.2V on IN3 (solid shape): 79.46,105.56 79.46,105.36 79.14,105.05 79.01,105.05 78.32,104.35 78,104.35 77.87,104.48 77.87,105.3 78.25,105.68 78.63,105.68 78.76,105.81 79.2,105.81
LX_1.2V on IN3 (solid shape): 86.95,106.95 86.95,106.71 86.7,106.45 86.51,106.45 86,106.95 84.67,106.95 84.54,107.08 84.54,107.53 84.6,107.59 84.6,107.59 84.72,107.71 86.19,107.71
LX_1.8VALW on BOTTOM (solid shape): 167.28,35.72 167.28,33.79 166.98,33.49 163.53,33.49 162.26,34.76 161.2,34.76 161.11,34.86 161.11,35.52 161.19,35.6 163.1,35.6 163.47,35.96 167.04,35.96
LX_3V on BOTTOM (solid shape): 172.68,45.81 172.68,45.17 173.95,43.9 174.14,43.9 174.39,43.65 174.39,43.01 174.33,42.95 173.4,42.95 172.36,41.91 172.36,40.85 172.17,40.66 169.37,40.66 169.18,40.85 169.18,43.9 171.15,45.87 172.61,45.87
LX_5V on BOTTOM (solid shape): 175.22,35.77 175.22,35.14 176.23,34.12 176.68,34.12 177.16,33.64 177.16,32.99 177.09,32.92 176.16,32.92 176.1,32.98 170.01,32.98 169.75,33.23 169.75,35.52 170.14,35.9 175.09,35.9
LX_+1.35VGPU on BOTTOM (solid shape): 152.42,94.89 152.42,93.81 152.55,93.69 153.31,93.69 153.5,93.5 153.5,92.35 154.9,90.96 154.9,90.95 155,90.85 155,90.37 154.91,90.28 153.52,90.28 153.15,89.91 153.15,88.89 152.74,88.48 150.77,88.48 150.58,88.67 150.58,94.45 151.15,95.02 152.29,95.02
LX_+1VALW on BOTTOM (solid shape): 147.15,47.65 147.15,46.19 147.4,45.93 148.04,45.93 148.1,45.87 148.1,45.17 148.1,45.09 149.41,43.78 149.47,43.73 149.47,43.05 149.36,42.95 147.78,42.95 147.53,42.7 147.53,41.62 147.4,41.49 145.18,41.49 144.93,41.74 144.93,47.78 145.12,47.97 146.83,47.97
MCT on TOP (solid shape): 20.93,118.57 20.93,117.22 20.43,116.72 20.43,107.79 20.33,107.69 19.41,107.69 19.3,107.8 19.3,118.41 19.66,118.77 20.73,118.77
MCT on BOTTOM (solid shape): 20.86,120.25 20.86,118.11 20.63,117.87 19.88,117.87 19.62,118.14 19.62,120.25 19.77,120.4 20.71,120.4
PHASE_CHG on TOP (solid shape): 207.73,34.95 207.73,31.96 208.11,31.58 209.63,31.58 209.82,31.39 209.82,30.31 209.63,30.12 206.65,30.12 206.01,30.76 206.01,34.95 206.2,35.14 207.54,35.14
PHASE_CHG on BOTTOM (solid shape): 210.33,35.14 210.33,30.38 209.76,29.81 206.08,29.81 205.95,29.93 205.95,32.15 205.38,32.73 204.81,32.73 204.68,32.85 204.68,35.39 204.81,35.52 209.95,35.52
PHASE_CHG on BOTTOM (solid shape): 199.08,35.62 199.08,35 199.03,34.95 197.44,34.95 197.25,35.14 196.11,35.14 196.06,35.18 196.06,35.29 196.12,35.34 197.07,35.34 197.12,35.39 197.37,35.39 197.38,35.39 197.44,35.46 198.25,35.46 198.33,35.46 198.52,35.65 199.05,35.65
PHASE_CHG on IN3 (solid shape): 207.6,34.82 207.6,34 207.41,33.81 206.52,33.81 206.2,34.12 206.2,34.37 206.78,34.95 207.48,34.95
PHASE_CHG on IN3 (solid shape): 197.41,35.55 200.08,35.55 200.17,35.45 200.17,35.01 199.98,34.82 199.28,34.82 199.22,34.88 197.44,34.88 197.25,35.08 197.25,35.39 197.41,35.55
RING2 on TOP (solid shape): 23.83,20.66 24.66,20.66 24.72,20.59 24.72,20.53 24.66,20.47 23.71,20.47 23.52,20.66 22.56,20.66 22.5,20.72 22.5,21.04 22.63,21.16 23.32,21.16
RING2 on BOTTOM (solid shape): 23.71,15.51 23.71,14.69 23.52,14.5 21.99,14.5 21.8,14.69 21.36,14.69 21.23,14.81 21.23,15.19 21.29,15.26 22.37,15.26 22.56,15.45 23.07,15.45 23.26,15.64 23.58,15.64
RING2 on IN3 (solid shape): 24.15,16.59 24.15,14.88 23.96,14.69 23.2,14.69 23.13,14.75 23.13,16.66 23.2,16.72 24.02,16.72
RING2 on IN3 (solid shape): 24.72,21.42 24.72,20.78 24.66,20.72 22.56,20.72 22.44,20.85 22.44,21.42 22.63,21.61 24.53,21.61
RING2_R on BOTTOM (solid shape): 22.18,16.08 22.18,15.64 22.05,15.51 20.32,15.51 19.43,14.62 16.28,14.62 16.02,14.88 16.02,15.39 16.34,15.7 17.23,15.7 17.48,15.45 19.32,15.45 20.09,16.21 22.05,16.21
SA_SNUB on TOP (solid shape): 147.21,55.86 147.21,55 147.12,54.91 146.26,54.91 146.13,54.78 144.43,54.78 144.35,54.86 144.35,55.87 144.43,55.95 147.12,55.95
SA_SW on TOP (solid shape): 147.26,54.57 147.26,52.28 147.03,52.06 144.67,52.06 144.44,52.28 144.44,54.1 144.61,54.27 145.86,54.27 146.31,54.71 147.12,54.71
SA_SW on BOTTOM (solid shape): 151.28,54.57 151.28,53.68 151.53,53.43 151.53,52.79 151.47,52.73 149.75,52.73 149.56,52.92 149.56,53.3 149.75,53.49 150.39,53.49 150.58,53.68 150.58,54.63 151.21,54.63
SA_SW on BOTTOM (solid shape): 149.12,56.92 149.12,56.79 147.34,55.01 147.34,54.32 146.89,53.87 146.89,51.65 146.51,51.27 143.08,51.27 142.98,51.37 142.98,52.35 143.88,52.35 143.88,53.11 142.98,53.11 142.98,54.47 144.16,55.65 146.51,55.65 148.35,57.49 148.55,57.49
SA_SW on IN3 (solid shape): 150.7,53.36 150.7,53.05 150.58,52.92 149.56,52.92 148.86,53.62 148.86,53.68 149.37,54.19 149.88,54.19
SA_SW on IN3 (solid shape): 148.67,55.4 148.67,54.76 148.35,54.44 147.4,54.44 147.21,54.25 146.26,54.25 146.2,54.32 146.2,55.27 146.45,55.52 148.55,55.52
SLEEVE on TOP (solid shape): 23.71,20.27 24.66,20.27 24.72,20.21 24.72,20.15 24.59,20.02 22.63,20.02 22.5,20.15 22.5,20.4 22.63,20.53 23.45,20.53
SLEEVE on BOTTOM (solid shape): 23.58,20.34 23.58,20.15 23.01,19.58 23.01,17.54 22.94,17.48 21.23,17.48 21.17,17.54 21.17,18.52 21.22,18.57 21.84,18.57 21.97,18.7 21.97,19.87 22.63,20.53 23.39,20.53
SLEEVE_R on TOP (solid shape): 15.99,17.82 15.99,16.06 15.92,15.99 15.19,15.99 15.1,16.08 15.1,17.82 15.21,17.94 15.87,17.94
SLEEVE_R on BOTTOM (solid shape): 16.15,17.61 17.04,17.61 17.29,17.86 19.66,17.86 20.16,17.35 21.93,17.35 21.99,17.29 21.99,16.59 21.83,16.43 19.8,16.43 19.39,16.85 17.48,16.85 17.23,16.59 14.94,16.59 14.63,16.91 14.63,17.99 14.69,18.05 15.7,18.05
SLEEVE_R on IN1 (solid shape): 15.9,19 15.9,17.04 15.64,16.78 15.07,16.78 14.75,17.1 14.75,19.07 14.94,19.26 15.64,19.26
SNUB_+1.35VGPU on BOTTOM (solid shape): 149.75,94.95 149.75,93.36 149.69,93.3 147.66,93.3 147.59,93.36 147.59,94.19 147.66,94.25 148.55,94.25 148.61,94.32 148.61,94.95 148.67,95.01 149.69,95.01
SNUB_+1VALW on BOTTOM (solid shape): 144.23,47.84 144.23,46.25 144.1,46.12 142.13,46.12 142,46.25 142,47.44 142.18,47.62 142.84,47.62 143.18,47.97 144.1,47.97
UG1_VGA on TOP (solid shape): 56.67,121.88 56.79,121.88 57.68,120.99 57.68,120.74 57.61,120.67 57.3,120.67 56.79,121.18 56.79,121.31 56.81,121.34 56.81,121.41 56.81,121.46 56.81,121.53 56.79,121.56 56.79,121.56 56.66,121.69 55.77,121.69 55.71,121.75 55.71,121.88 55.77,121.94 56.61,121.94
UG1_VGA on BOTTOM (solid shape): 74.12,111.09 74.12,109.81 74.03,109.71 72.94,109.71 72.79,109.86 72.79,111.02 72.98,111.21 74,111.21
UG1_VGA on IN1 (solid shape): 58.12,120.61 58.44,120.61 58.63,120.42 58.63,119.91 58.57,119.85 57.8,119.85 56.72,120.93 56.72,121.31 56.98,121.56 57.17,121.56
UG1_VGA on IN1 (solid shape): 74.12,111.34 74.12,110.07 74,109.94 73.99,109.94 73.91,109.87 72.87,109.87 72.54,110.2 72.54,111.4 72.66,111.53 73.93,111.53
UG2_VGA on TOP (solid shape): 57.68,125.31 57.68,125.12 57.11,124.55 55.73,124.55 55.67,124.61 55.67,124.68 55.73,124.74 55.78,124.74 56.66,124.74 57.04,125.12 57.04,125.18 57.3,125.44 57.55,125.44
UG2_VGA on BOTTOM (solid shape): 74.17,128.2 74.17,127.07 73.93,126.83 72.85,126.83 72.79,126.9 72.79,128.22 72.89,128.32 74.05,128.32
UG2_VGA on IN1 (solid shape): 73.93,128.23 73.93,126.9 73.81,126.77 72.85,126.77 72.73,126.9 72.73,128.17 72.98,128.42 73.74,128.42
UG2_VGA on IN1 (solid shape): 58.88,126.52 58.88,126.39 57.23,124.74 57.23,124.67 57.11,124.55 56.91,124.55 56.79,124.67 56.79,125.63 57.8,126.64 58.76,126.64
UG_1.2V on BOTTOM (solid shape): 79.14,106.7 79.14,106.2 79.01,106.07 78.5,106.07 78.38,105.94 78.19,105.94 78.06,106.07 78.06,106.89 78.19,107.02 78.82,107.02
UG_1.2V on BOTTOM (solid shape): 87.66,107.39 87.66,107.13 87.64,107.11 87.64,106.1 87.57,106.03 87.49,106.03 87.43,106.09 87.43,106.86 86.76,107.53 86.76,107.85 86.85,107.94 87.11,107.94
UG_1.2V on IN3 (solid shape): 79.05,106.86 79.49,106.86 79.59,106.76 79.59,106.38 79.24,106.03 78.54,106.03 78.44,105.94 78.19,105.94 78,106.13 78,106.77 78.25,107.02 78.89,107.02
UG_1.2V on IN3 (solid shape): 87.62,107.62 87.65,107.56 87.65,107.21 87.46,107.02 87.14,107.02 86.26,107.9 85.43,107.9 85.36,107.97 85.36,108.48 85.43,108.55 85.43,108.6 85.53,108.7 86.54,108.7
UGATE_CHG on BOTTOM (solid shape): 197.31,34.82 197.39,34.82 198.33,34.82 198.39,34.76 198.39,33.81 197.76,33.81 197.12,34.44 197.12,34.5 196.89,34.74 196.13,34.74 196.07,34.79 196.07,34.92 196.11,34.95 197.19,34.95
USB20_VCCA on BOTTOM (solid shape): 173.88,18.12 173.88,13.61 170.9,10.62 170.9,2.75 170.52,2.37 167.98,2.37 167.72,2.62 167.72,12.1 170.12,14.5 170.12,18.05 170.51,18.44 173.56,18.44
USB20_VCCA on BOTTOM (solid shape): 127.84,12.03 127.92,11.99 127.94,11.9 128.29,11.47 128.64,11.9 128.66,11.99 128.74,12.03 128.77,12.03 133.36,7.44 133.36,7.38 134.28,6.46 134.28,6.37 134.24,6.28 134.14,6.28 133.61,5.96 134.14,5.65 134.24,5.64 134.28,5.56 134.28,5.16 134.02,4.9 134.02,2.95 133.52,2.46 131.35,2.46 131.19,2.62 131.19,6.52 128.28,9.43 128.28,9.75 127.78,10.25 127.15,10.25 126.96,10.44 126.96,11.71 127.27,12.03
USB20_VCCA on IN2 (solid shape): 135.39,3.03 135.39,1.78 134.91,1.3 133.71,1.3 132.21,2.8 132.21,4.15 132.34,4.27 134.14,4.27
USB20_VCCA on IN2 (solid shape): 169.82,4.78 169.82,3.13 169.63,2.94 165.88,2.94 165.63,3.19 165.63,4.91 165.76,5.03 169.57,5.03
USB30_VCCA on TOP (solid shape): 17.86,67.84 17.86,64.66 17.48,64.28 17.48,62.82 17.42,62.76 15.57,62.76 15.39,62.57 14.5,62.57 14.18,62.89 14.18,65.46 14.19,65.48 14.19,65.69 16.53,68.03 17.67,68.03
USB30_VCCA on TOP (solid shape): 18.64,50.76 18.64,49.07 18.4,48.83 17.61,48.83 17.23,48.45 17.23,47.01 17.61,46.63 17.61,42.92 17.54,42.86 17.54,41.62 17.54,41.61 17.54,41.29 17.42,41.17 15.57,41.17 15.32,40.92 14.43,40.92 14.12,41.24 14.12,44.17 14.69,44.74 14.69,50.79 14.95,51.05 18.36,51.05
USB30_VCCA on BOTTOM (solid shape): 18.23,70.84 18.23,61.9 18.06,61.73 14.72,61.73 14.08,62.37 14.08,64.72 15.13,65.78 15.13,69.42 14.43,70.12 14.43,71.07 14.63,71.27 17.8,71.27
USB30_VCCA on BOTTOM (solid shape): outline of 296 points within 14.06,40.9 19.98,51.89
N17237617 on TOP (solid shape): 202.96,30.25 202.96,28.79 202.77,28.6 198.2,28.6 197.76,29.05 197.76,30.37 197.82,30.44 202.77,30.44
N17237617 on BOTTOM (solid shape): 205.38,31.39 205.38,29.11 204.93,28.66 204.43,28.66 203.09,27.33 203.09,26.19 202.16,25.26 201.59,25.26 201.59,25.77 200.89,25.77 200.89,25.26 200.39,25.26 200.39,25.77 199.69,25.77 199.69,25.26 199.13,25.26 198.65,25.74 198.65,28.22 197.76,29.11 197.76,30.37 197.82,30.44 202.9,30.44 203.03,30.57 203.03,31.46 203.16,31.58 205.19,31.58
N17415515 on TOP (solid shape): 170.15,124.93 170.15,122.27 169.6,121.72 169.6,120.81 169.25,119.77 169.1,119.39 169.07,119.36 169.07,119.34 168.93,118.97 168.86,118.66 168.86,118.25 168.6,117.99 167.65,117.99 166.83,118.8 166.83,120.25 167.37,120.25 167.37,120.75 166.83,120.75 166.83,121.05 167.37,121.05 167.37,121.55 166.83,121.55 166.83,122.2 165.88,123.15 165.88,124.99 166.2,125.31 169.77,125.31
N20135074 on TOP (solid shape): 71.52,115.4 71.52,113.88 71.39,113.75 69.55,113.75 69.36,113.94 69.36,115.4 69.49,115.53 71.39,115.53
N20135197 on TOP (solid shape): 69.74,128.99 69.74,127.34 69.61,127.21 68.66,127.21 68.54,127.34 68.54,128.17 68.28,128.42 67.39,128.42 67.27,128.55 67.27,129.34 67.33,129.4 69.33,129.4
N20135251 on TOP (solid shape): 53.55,127.72 53.55,126.26 53.61,126.2 53.61,125.31 53.55,125.25 52.66,125.25 52.6,125.31 52.6,126.58 52.53,126.64 52.53,127.72 52.6,127.79 53.49,127.79
N28484451 on TOP (solid shape): 185.95,23.66 185.95,22.44 185.81,22.31 185,22.31 184.61,21.93 184.61,21.54 184.49,21.42 183.74,21.42 183.7,21.46 183.7,22.41 183.48,22.62 183.48,23.09 183.61,23.21 184.19,23.21 184.72,23.75 185.86,23.75
N28712229 on BOTTOM (solid shape): 161.15,80.19 161.33,80.19 161.61,79.91 162.32,79.91 162.33,79.9 162.5,79.9 162.54,79.86 162.54,79.32 162.43,79.21 161.36,79.21 160.64,79.93 160.64,80.13 160.7,80.19 161.15,80.19
N28712232 on BOTTOM (solid shape): 161.82,81.11 162.66,81.11 162.67,81.11 162.67,80.23 162.6,80.16 162.07,80.16 161.31,80.92 160.67,80.92 160.67,80.93 160.62,80.97 160.62,81.13 160.69,81.19 161.74,81.19
N28714507 on BOTTOM (solid shape): 165.25,119.2 165.25,117.66 165.16,117.57 162.01,117.57 161.43,116.99 161.43,115.94 161.42,115.88 161.43,115.82 161.43,114.17 161.17,113.92 159.81,113.92 159.42,114.31 159.42,117.78 161,119.37 165.08,119.37
N28714507 on IN2 (solid shape): 165.25,119.2 165.25,117.66 165.16,117.57 162.01,117.57 161.43,116.99 161.43,115.94 161.42,115.88 161.43,115.82 161.43,114.17 161.17,113.92 159.81,113.92 159.42,114.31 159.42,117.78 161,119.37 165.08,119.37
N28714507 on IN3 (solid shape): 165.25,119.2 165.25,117.66 165.16,117.57 162.01,117.57 161.43,116.99 161.43,115.94 161.42,115.88 161.43,115.82 161.43,114.17 161.17,113.92 159.81,113.92 159.42,114.31 159.42,117.78 161,119.37 165.08,119.37
N28714606 on BOTTOM (solid shape): 206.97,29.36 206.97,28.6 206.84,28.47 206.01,28.47 205.89,28.6 205.89,29.36 206.01,29.49 206.84,29.49
N28714606 on BOTTOM (solid shape): 200.47,34.68 200.47,33.79 200.31,33.63 200.12,33.63 199.98,33.77 199.2,33.77 199.14,33.84 199.14,34.66 199.26,34.79 199.84,34.79 199.92,34.87 200.29,34.87
N28714606 on IN3 (solid shape): 206.97,29.23 206.97,28.54 206.84,28.41 205,28.41 204.81,28.6 204.81,29.11 205.12,29.42 206.77,29.42
N28714606 on IN3 (solid shape): 200.46,34.54 200.46,33.77 200.31,33.62 199.61,33.62 199.41,33.42 199.41,32.73 199.28,32.6 198.77,32.6 198.52,32.85 198.52,34.27 198.91,34.66 200.34,34.66
N28714612 on BOTTOM (solid shape): 196.97,34.47 196.97,34.34 197.63,33.68 197.63,33.68 197.88,33.42 198.39,33.42 198.39,32.54 197.76,32.54 196.49,33.81 196.49,34.06 196.23,34.31 196.15,34.31 196.07,34.39 196.07,34.49 196.12,34.54 196.9,34.54
N28714617 on BOTTOM (solid shape): 166.37,117.21 166.37,112.76 166.28,112.67 164.17,112.67 163.4,111.91 163.4,111.15 161.88,111.15 161.88,110.51 163.4,110.51 163.4,109.82 163.28,109.69 161.18,109.69 160.86,110.01 160.86,111.85 160.87,111.87 160.87,111.98 161.75,112.85 161.75,115.53 162.14,115.88 161.75,116.23 161.75,117.05 162.13,117.44 166.15,117.44
N28714693 on BOTTOM (solid shape): 217.44,34.06 217.44,26.57 216.71,25.84 214.24,25.84 214.23,25.84 214.17,25.84 214.01,25.99 214.01,27.52 213.38,27.52 213.38,25.99 213.19,25.99 212.81,25.61 212.81,25.11 212.04,24.34 209.39,24.34 209.19,24.55 209.19,28.15 210.97,29.93 210.97,31.46 211.07,31.71 210.97,31.96 210.97,33.68 211.85,34.57 216.93,34.57
N28714856 on BOTTOM (solid shape): 162.26,71.52 162.4,71.52 162.58,71.34 162.58,70.46 162.57,70.45 161.93,70.45 161.85,70.53 161.85,70.72 161.3,71.27 160.66,71.27 160.61,71.32 160.61,71.47 160.66,71.52 162.26,71.52
N28718522 on BOTTOM (solid shape): 154.96,54.25 154.96,52.47 154.7,52.22 153.12,52.22 153.01,52.22 152.94,52.29 152.94,52.41 153,52.47 153.82,52.47 154.13,52.79 154.13,53.55 153.82,53.87 153.82,54.32 153.94,54.44 154.77,54.44
N32012960 on BOTTOM (solid shape): 151.53,51.33 151.53,50.7 151.4,50.57 149.94,50.57 149.75,50.76 149.75,51.2 150.01,51.46 151.4,51.46
N32012960 on BOTTOM (solid shape): 148.48,54.51 148.48,53.17 147.72,52.41 147.4,52.41 147.15,52.67 147.15,53.55 147.53,53.94 147.53,54.89 147.72,55.08 147.91,55.08
N32012960 on IN3 (solid shape): 148.29,53.55 148.29,51.84 148.1,51.65 147.4,51.65 147.28,51.78 147.28,53.74 147.4,53.87 147.97,53.87
N32012960 on IN3 (solid shape): 150.89,51.08 150.89,50.57 150.64,50.32 148.93,50.32 148.67,50.57 148.67,51.08 148.99,51.4 150.58,51.4
N32012964 on BOTTOM (solid shape): 146.07,56.92 146.07,56.79 145.56,56.28 144.54,56.28 144.35,56.48 144.35,56.82 144.38,56.84 144.54,56.94 144.71,57.05 145.94,57.05
N32012964 on BOTTOM (solid shape): 153.94,53.52 153.94,52.92 153.74,52.72 152.98,52.72 152.89,52.81 152.89,53.58 152.97,53.67 153.8,53.67
N32012964 on IN3 (solid shape): 147.34,56.98 147.34,56.22 147.21,56.09 144.8,56.09 144.42,56.48 144.42,56.86 144.67,57.11 147.21,57.11
N32012964 on IN3 (solid shape): 153.94,54.51 153.94,53.24 153.88,53.17 152.99,53.17 152.8,53.36 152.8,54.38 153.12,54.7 153.75,54.7
N39282118 on BOTTOM (solid shape): 156.27,37.99 156.78,37.99 156.78,38.51 157.07,38.51 157.07,37.99 157.58,37.99 157.58,38.51 158.06,38.51 158.77,37.81 159.66,37.81 159.72,37.74 159.72,36.92 159.63,36.82 159.31,36.82 158.97,36.48 158.97,34.88 158.88,34.8 157.9,34.8 155.66,37.04 155.66,38.37 155.8,38.51 156.27,38.51
N40598435 on BOTTOM (solid shape): 173.82,47.33 173.82,46.75 173.76,46.69 172.87,46.69 172.75,46.58 172.75,46.32 172.55,46.12 172.04,46.12 171.91,46.25 171.91,46.69 172.61,47.39 173.76,47.39
N40598492 on BOTTOM (solid shape): 177.13,32.2 177.13,31.64 177.06,31.56 175.74,31.56 175.58,31.72 175.58,31.97 175.69,32.07 175.86,32.07 176.07,32.28 177.06,32.28
N40598500 on BOTTOM (solid shape): 176.17,36.66 176.17,35.33 176.1,35.27 175.53,35.27 175.41,35.39 175.41,35.96 175.15,36.22 174.64,36.22 174.58,36.28 174.58,36.73 174.64,36.79 176.04,36.79

Small or netless copper shapes (teardrops, artwork), in the pictures only: 57 on TOP, 148 on BOTTOM, 1 on GND1, 1 on GND2

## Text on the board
Ref Des/Silkscreen Bottom: SPK | 15"(M2.5X5L) | 17"(M2X3L) | RTC | 17" | (M2X3L) | H11 | KB | TP | BL | LED | IO | Fan | ODD | HDD | BATTERY | DIMM B | SUPPORT DDR4 | SODIMM-ONLY | SODIMM-ONLY SUPPORT DDR4 | DIMM A | EDP
User.Comments: LAD801P | Saijuan | 2017-06-17 | 2016-06-17 | BAL20 | 1.0(A00)
Ref Des/Silkscreen Top: OPTANE | DC IN | PWR
COMPVAL_TYPE_BOTTOM: LAYER | NAME | L3 | L1 | L2 | L5 | L4 | L6 | L7 | L8 | LA-D801P | TOP | GND1 | IN2 | IN3 | GND2 | IN1 | BOT | VCC | LS-XXXXP
